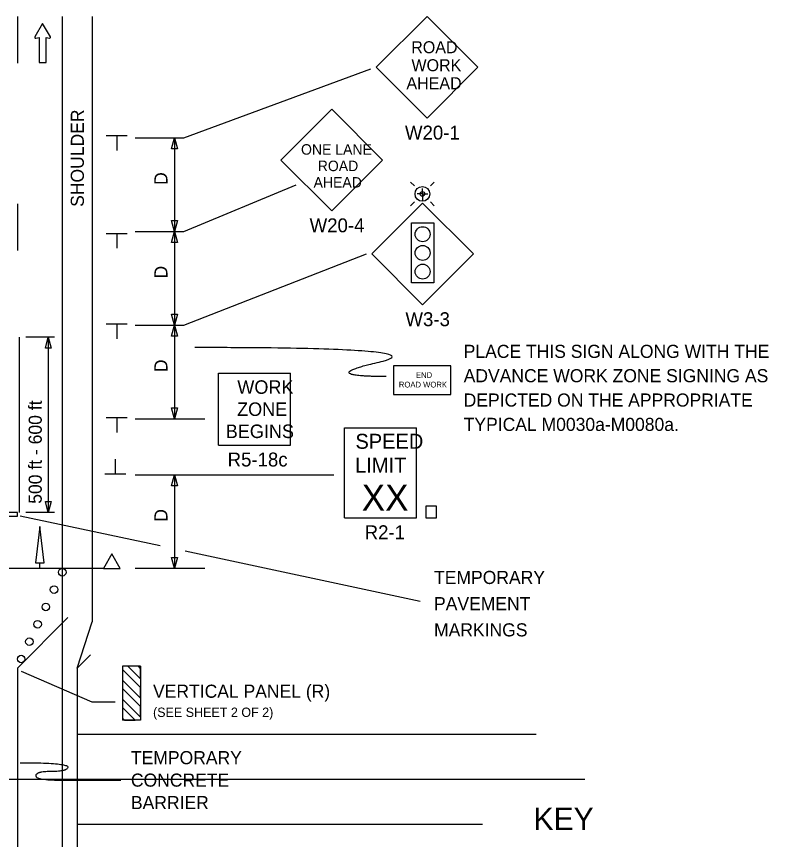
# Model space of a CAD drawing. Extents: x 16520 to 18479, y 5662 to 6927.
# Drawn here: x 16953.3 to 17355.2, y 6459.8 to 6899.4 of the extents above; entities that cross this region are included whole.
import ezdxf

# ---------------------------------------------------------------- set-up
doc = ezdxf.new("R2010")
doc.units = 0
for name, color, linetype in [('ALI_LEGAL_EX', 7, 'Continuous'), ('MT_SCRATCH_LEVEL_E', 7, 'Continuous'), ('PAVT_EDGE_EX', 7, 'Continuous'), ('TRAFFIC_SIGNS_PR', 7, 'Continuous'), ('TYPICAL_TEXT_DIMEN_EX', 7, 'Continuous'), ('TYPICAL_TEXT_DIMEN_PR', 7, 'Continuous')]:
    doc.layers.add(name, color=color, linetype=linetype)

msp = doc.modelspace()

# ---------------------------------------------------------------- linework, layer by layer
at = {"layer": 'ALI_LEGAL_EX'}
for points in [[(16953.78, 6899.43), (16953.78, 6874.43)], [(16953.78, 6799.43), (16953.78, 6774.43)], [(16954.78, 6728.2), (16954.78, 6634.57)]]:
    msp.add_lwpolyline(points, dxfattribs=at)
at = {"layer": 'MT_SCRATCH_LEVEL_E'}
for p, q in [((16967.25, 6895.73), (16963.14, 6888.49)), ((16967.25, 6895.73), (16963.14, 6888.49)), ((16971.4, 6888.49), (16967.25, 6895.73)), ((16971.4, 6888.49), (16967.25, 6895.73)), ((16963.62, 6887.8), (16965.4, 6888.12)), ((16963.62, 6887.8), (16965.4, 6888.12)), ((16965.4, 6888.12), (16965.4, 6874.86)), ((16965.4, 6888.12), (16965.4, 6874.86)), ((16969.14, 6874.86), (16969.14, 6888.12)), ((16969.14, 6888.12), (16970.92, 6887.8)), ((16969.14, 6874.86), (16969.14, 6888.12)), ((16969.14, 6888.12), (16970.92, 6887.8)), ((16965.4, 6874.86), (16969.14, 6874.86)), ((16965.4, 6874.86), (16969.14, 6874.86))]:
    msp.add_line(p, q, dxfattribs=at)
for centre, start, end in [((16963.54, 6888.26), 150.4248, 279.9638), ((16963.54, 6888.26), 150.4248, 279.9638), ((16970.99, 6888.26), 260.0362, 29.7731), ((16970.99, 6888.26), 260.0362, 29.7731)]:
    msp.add_arc(centre, 0.463, start, end, dxfattribs=at)
at = {"layer": 'PAVT_EDGE_EX'}
for p, q in [((16977.78, 6899.43), (16977.78, 6077.5)), ((16993.78, 6899.43), (16993.78, 6576.06)), ((16953.78, 6551.35), (16980.8, 6578.37)), ((16985.78, 6551.35), (16993.78, 6576.06)), ((16985.78, 6551.35), (16992.85, 6558.43)), ((16953.78, 6551.35), (16953.78, 6419.96)), ((16985.78, 6551.35), (16985.78, 6419.96)), ((16985.78, 6516.09), (17230.97, 6516.09)), ((16760.93, 6492.09), (17256.97, 6492.09)), ((16985.78, 6468.09), (17202.32, 6468.09))]:
    msp.add_line(p, q, dxfattribs=at)
for points in [[(17060.93, 6492.09), (17085.93, 6492.09)], [(17160.93, 6492.09), (17185.93, 6492.09)]]:
    msp.add_lwpolyline(points, dxfattribs=at)
at = {"layer": 'TRAFFIC_SIGNS_PR'}
for p, q in [((17172.72, 6899.41), (17145.57, 6872.26)), ((17199.87, 6872.26), (17172.72, 6899.41)), ((17145.57, 6872.26), (17172.72, 6845.1)), ((17172.72, 6845.1), (17199.87, 6872.26)), ((17121.76, 6849.9), (17094.61, 6822.74)), ((17148.92, 6822.74), (17121.76, 6849.9)), ((17094.61, 6822.74), (17121.76, 6795.59)), ((17121.76, 6795.59), (17148.92, 6822.74)), ((17165.93, 6808.95), (17163.9, 6810.98)), ((17174.5, 6808.95), (17176.53, 6810.98)), ((17170.21, 6804.67), (17170.21, 6807.55)), ((17170.21, 6804.67), (17167.34, 6804.67)), ((17170.21, 6804.67), (17170.21, 6800.73)), ((17170.21, 6804.67), (17173.09, 6804.67)), ((17170.28, 6799.75), (17143.13, 6772.6)), ((17165.93, 6800.39), (17163.9, 6798.36)), ((17197.44, 6772.6), (17170.28, 6799.75)), ((17176.53, 6798.36), (17174.5, 6800.39)), ((17143.13, 6772.6), (17170.28, 6745.45)), ((17170.28, 6745.45), (17197.44, 6772.6)), ((17061.31, 6670.51), (17061.31, 6708.91)), ((17061.31, 6708.91), (17099.71, 6708.91)), ((17099.71, 6670.51), (17099.71, 6708.91)), ((17128.67, 6679.66), (17167.07, 6679.66)), ((17128.67, 6631.66), (17128.67, 6679.66)), ((17167.07, 6631.66), (17167.07, 6679.66)), ((17061.31, 6670.51), (17099.71, 6670.51)), ((17128.67, 6631.66), (17167.07, 6631.66)), ((16965.78, 6604.57), (16965.78, 6607.59)), ((16999.78, 6604.57), (16907.78, 6604.57)), ((17019.53, 6552.35), (17009.93, 6552.35)), ((17009.93, 6552.35), (17009.93, 6523.55)), ((17019.53, 6552.35), (17009.93, 6552.35)), ((17009.93, 6552.35), (17009.93, 6523.55)), ((17019.53, 6541.08), (17009.93, 6550.68)), ((17019.53, 6541.08), (17009.93, 6550.68)), ((17019.53, 6545.6), (17012.78, 6552.35)), ((17019.53, 6545.6), (17012.78, 6552.35)), ((17019.53, 6551.26), (17018.44, 6552.35)), ((17019.53, 6551.26), (17018.44, 6552.35)), ((17019.53, 6552.35), (17019.53, 6523.55)), ((17019.53, 6552.35), (17019.53, 6523.55)), ((17019.53, 6535.42), (17009.93, 6545.02)), ((17019.53, 6535.42), (17009.93, 6545.02)), ((17019.53, 6530.9), (17009.93, 6540.5)), ((17019.53, 6530.9), (17009.93, 6540.5)), ((17019.53, 6525.24), (17009.93, 6534.84)), ((17019.53, 6525.24), (17009.93, 6534.84)), ((17016.7, 6523.55), (17009.93, 6530.31)), ((17016.7, 6523.55), (17009.93, 6530.31)), ((17011.04, 6523.55), (17009.93, 6524.66)), ((17011.04, 6523.55), (17009.93, 6524.66)), ((17019.53, 6523.55), (17009.93, 6523.55)), ((17019.53, 6523.55), (17009.93, 6523.55))]:
    msp.add_line(p, q, dxfattribs=at)
for points in [[(17176.35, 6757.15), (17164.35, 6757.15), (17164.35, 6789.15), (17176.35, 6789.15)], [(17154.75, 6697.48), (17185.47, 6697.48), (17185.47, 6712.84), (17154.75, 6712.84)], [(16929.78, 6634.57), (16929.78, 6632.57), (16953.78, 6632.57), (16953.78, 6634.57)], [(17172.09, 6631.66), (17177.68, 6631.66), (17177.68, 6637.83), (17172.09, 6637.83)], [(16968.03, 6607.59), (16965.78, 6627.01), (16963.53, 6607.59)], [(17008.78, 6604.57), (17004.28, 6612.37), (16999.78, 6604.57)], [(17019.53, 6541.08), (17009.93, 6550.68), (17009.93, 6545.02), (17019.53, 6535.42)], [(17019.53, 6541.08), (17009.93, 6550.68), (17009.93, 6545.02), (17019.53, 6535.42)], [(17018.44, 6552.35), (17012.78, 6552.35), (17019.53, 6545.6), (17019.53, 6551.26)], [(17018.44, 6552.35), (17012.78, 6552.35), (17019.53, 6545.6), (17019.53, 6551.26)], [(17019.53, 6530.9), (17009.93, 6540.5), (17009.93, 6534.84), (17019.53, 6525.24)], [(17019.53, 6530.9), (17009.93, 6540.5), (17009.93, 6534.84), (17019.53, 6525.24)], [(17009.93, 6530.31), (17009.93, 6524.66), (17011.04, 6523.55), (17016.7, 6523.55)], [(17009.93, 6530.31), (17009.93, 6524.66), (17011.04, 6523.55), (17016.7, 6523.55)]]:
    msp.add_lwpolyline(points, close=True, dxfattribs=at)
for centre, radius in [((17170.21, 6804.67), 3.94), ((17170.21, 6804.67), 1.28), ((17170.35, 6783.14), 4), ((17170.35, 6773.14), 4), ((17170.35, 6763.14), 4), ((16977.78, 6602.57), 2), ((16973.38, 6593.3), 2), ((16968.98, 6584.04), 2), ((16964.58, 6574.78), 2), ((16960.18, 6565.51), 2), ((16955.78, 6556.25), 2)]:
    msp.add_circle(centre, radius, dxfattribs=at)
msp.add_open_spline([(17150.89, 6707.11), (17113.1, 6707.11), (17181.12, 6722.59), (17048.59, 6722.59)], degree=2, dxfattribs=at)
at = {"layer": 'TYPICAL_TEXT_DIMEN_PR'}
for p, q in [((17042.78, 6834.57), (17142.57, 6871.45)), ((17012.53, 6835.68), (17001.28, 6835.68)), ((17006.91, 6835.68), (17006.91, 6827.89)), ((17016.78, 6834.57), (17042.78, 6834.57)), ((17036.21, 6828.71), (17037.78, 6834.57)), ((17037.78, 6834.57), (17037.78, 6784.57)), ((17037.78, 6834.57), (17039.35, 6828.71)), ((17037.78, 6828.71), (17036.21, 6828.71)), ((17039.35, 6828.71), (17037.78, 6828.71)), ((17042.78, 6784.57), (17102.74, 6809.53)), ((17037.78, 6784.57), (17036.21, 6790.43)), ((17036.21, 6790.43), (17037.78, 6790.43)), ((17037.78, 6790.43), (17039.35, 6790.43)), ((17039.35, 6790.43), (17037.78, 6784.57)), ((17012.53, 6783.38), (17001.28, 6783.38)), ((17006.91, 6783.38), (17006.91, 6775.6)), ((17016.78, 6784.57), (17042.78, 6784.57)), ((17036.21, 6778.71), (17037.78, 6784.57)), ((17037.78, 6784.57), (17037.78, 6734.57)), ((17037.78, 6784.57), (17039.35, 6778.71)), ((17037.78, 6778.71), (17036.21, 6778.71)), ((17039.35, 6778.71), (17037.78, 6778.71)), ((17042.78, 6734.57), (17140.34, 6772.73)), ((17037.78, 6734.57), (17036.21, 6740.43)), ((17036.21, 6740.43), (17037.78, 6740.43)), ((17037.78, 6740.43), (17039.35, 6740.43)), ((17039.35, 6740.43), (17037.78, 6734.57)), ((17012.53, 6735.05), (17001.28, 6735.05)), ((17006.91, 6735.05), (17006.91, 6727.26)), ((17016.78, 6734.57), (17042.78, 6734.57)), ((17036.21, 6728.71), (17037.78, 6734.57)), ((17037.78, 6734.57), (17037.78, 6684.57)), ((17037.78, 6734.57), (17039.35, 6728.71)), ((16973.59, 6728.2), (16958.31, 6728.2)), ((16968.72, 6722.34), (16970.29, 6728.2)), ((16970.29, 6728.2), (16970.29, 6634.57)), ((16970.29, 6728.2), (16971.86, 6722.34)), ((17037.78, 6728.71), (17036.21, 6728.71)), ((17039.35, 6728.71), (17037.78, 6728.71)), ((16970.29, 6722.34), (16968.72, 6722.34)), ((16971.86, 6722.34), (16970.29, 6722.34)), ((17037.78, 6684.57), (17036.21, 6690.43)), ((17036.21, 6690.43), (17037.78, 6690.43)), ((17037.78, 6690.43), (17039.35, 6690.43)), ((17039.35, 6690.43), (17037.78, 6684.57)), ((17012.53, 6685.05), (17001.28, 6685.05)), ((17006.91, 6685.05), (17006.91, 6677.26)), ((17016.78, 6684.57), (17054.02, 6684.57)), ((17006.14, 6655.16), (17006.14, 6662.94)), ((17000.52, 6655.16), (17011.77, 6655.16)), ((17016.78, 6654.68), (17122.84, 6654.68)), ((17036.21, 6648.82), (17037.78, 6654.68)), ((17037.78, 6654.68), (17037.78, 6604.68)), ((17037.78, 6654.68), (17039.35, 6648.82)), ((17037.78, 6648.82), (17036.21, 6648.82)), ((17039.35, 6648.82), (17037.78, 6648.82)), ((16970.29, 6634.57), (16968.72, 6640.43)), ((16968.72, 6640.43), (16970.29, 6640.43)), ((16970.29, 6640.43), (16971.86, 6640.43)), ((16971.86, 6640.43), (16970.29, 6634.57)), ((16973.59, 6634.57), (16958.31, 6634.57)), ((16955.27, 6632.78), (17030.03, 6616.85)), ((17043.46, 6613.99), (17169.05, 6587.22)), ((17037.78, 6604.68), (17036.21, 6610.54)), ((17036.21, 6610.54), (17037.78, 6610.54)), ((17037.78, 6610.54), (17039.35, 6610.54)), ((17039.35, 6610.54), (17037.78, 6604.68)), ((17016.78, 6604.68), (17054.02, 6604.68)), ((16955.78, 6549.81), (16993.57, 6533.37)), ((16955.78, 6549.81), (16993.57, 6533.37)), ((16993.57, 6533.37), (17006.03, 6533.37)), ((16993.57, 6533.37), (17006.03, 6533.37))]:
    msp.add_line(p, q, dxfattribs=at)
msp.add_open_spline([(16955.22, 6500.88), (16980.8, 6500.88), (16980.8, 6496.18), (16963.59, 6496.18), (16963.59, 6491.47), (16996.58, 6491.47), (17009.05, 6491.47)], degree=2, dxfattribs=at)

# ---------------------------------------------------------------- texts
at = {"layer": 'TRAFFIC_SIGNS_PR'}
for s, height, p in [('ROAD', 6.4, (17164.26, 6879.79)), ('WORK', 6.4, (17164.37, 6870.19)), ('AHEAD', 6.4, (17161.68, 6860.59)), ('W20-1', 7.44, (17160.89, 6833.67)), ('ONE LANE', 5.6, (17105.35, 6825.61)), ('ROAD', 5.6, (17114.3, 6816.82)), ('AHEAD', 5.6, (17112.06, 6808.02)), ('W20-4', 7.44, (17109.94, 6784.15)), ('W3-3', 7.44, (17161.15, 6734.01)), ('PLACE THIS SIGN ALONG WITH THE', 7, (17192.28, 6717.06)), ('END', 3.065, (17166.75, 6706.38)), ('ADVANCE WORK ZONE SIGNING AS', 7, (17192.28, 6704.06)), ('WORK', 7.217, (17071.31, 6697.88)), ('ROAD WORK', 3.065, (17157.63, 6701.27)), ('DEPICTED ON THE APPROPRIATE', 7, (17192.28, 6691.06)), ('ZONE', 7.217, (17071.19, 6686.07)), ('TYPICAL M0030a-M0080a.', 7, (17192.28, 6678.06)), ('BEGINS', 7.217, (17065.12, 6674.26)), ('SPEED', 8, (17134.44, 6668.52)), ('R5-18c', 7.44, (17066.12, 6659.07)), ('LIMIT', 8, (17134.28, 6655.72)), ('XX', 14.031, (17137.78, 6635.42)), ('R2-1', 7.44, (17139.35, 6620.22))]:
    msp.add_text(s, height=height, dxfattribs=at).set_placement(p)
at = {"layer": 'TYPICAL_TEXT_DIMEN_EX'}
msp.add_text('KEY', height=12, dxfattribs=at).set_placement((17229.62, 6464.89))
at = {"layer": 'TYPICAL_TEXT_DIMEN_PR'}
for s, p in [('SHOULDER', (16989.31, 6797.73)), ('D', (17034, 6809.45)), ('D', (17034, 6759.45)), ('D', (17034, 6709.45)), ('500 ft - 600 ft', (16966.8, 6639.16)), ('D', (17034, 6629.56))]:
    msp.add_text(s, height=7, rotation=90, dxfattribs=at).set_placement(p)
for s, height, p in [('TEMPORARY', 7, (17176.44, 6596.31)), ('PAVEMENT', 7, (17176.44, 6582.31)), ('MARKINGS', 7, (17176.44, 6568.31)), ('VERTICAL PANEL (R)', 7, (17026.27, 6535.55)), ('VERTICAL PANEL (R)', 7, (17026.27, 6535.55)), ('(SEE SHEET 2 OF 2)', 5, (17026.27, 6525.3)), ('(SEE SHEET 2 OF 2)', 5, (17026.27, 6525.3)), ('TEMPORARY', 7, (17014.45, 6500.07)), ('CONCRETE', 7, (17014.45, 6488.07)), ('BARRIER', 7, (17014.45, 6476.07))]:
    msp.add_text(s, height=height, dxfattribs=at).set_placement(p)

doc.saveas('drawing.dxf')
